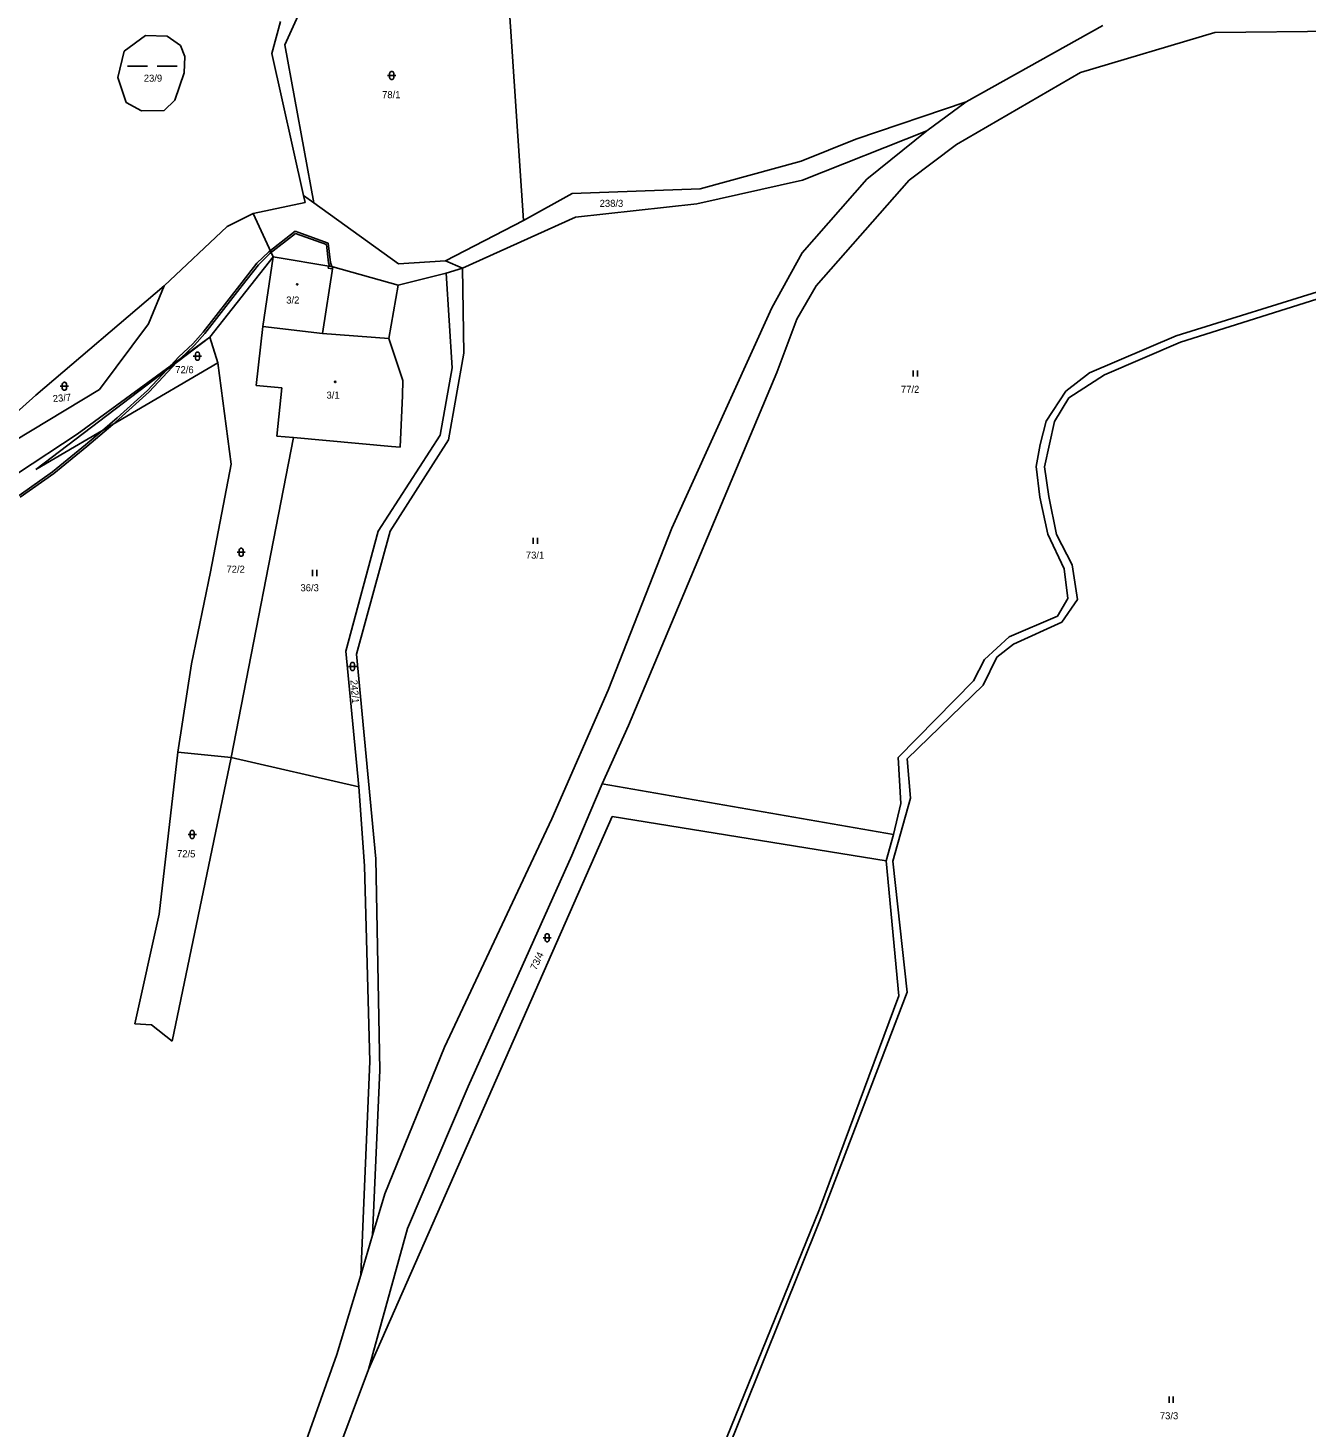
# Model space of a CAD drawing. Extents: x -811039 to -805820, y -1161436 to -1155864.
# Drawn here: x -809942.6 to -809634.1, y -1160806.6 to -1160468.8 of the extents above; entities that cross this region are included whole.
import ezdxf

# ---------------------------------------------------------------- set-up
doc = ezdxf.new("R2010")
doc.units = 0
for name, color, linetype in [('Default', 7, 'Continuous'), ('Hranice parcel', 7, 'Continuous'), ('Parcelní čísla', 7, 'Continuous'), ('Vnitřní kresba', 7, 'Continuous'), ('Věcná břemena k části', 7, 'Continuous'), ('Značky budov', 7, 'Continuous'), ('Značky kultur', 7, 'Continuous')]:
    doc.layers.add(name, color=color, linetype=linetype)

# ---------------------------------------------------------------- blocks, each defined once
blk = doc.blocks.new('306')
at = {"layer": 'Default'}
for p, q in [((-0.5, 1.5), (-0.5, 0)), ((0.5, 0), (0.5, 1.5))]:
    blk.add_line(p, q, dxfattribs=at)
blk = doc.blocks.new('316')
at = {"layer": 'Default'}
for points in [[(-1, 1), (0.27, 1), (1, 1)], [(-0.5, 1.5), (-0.4, 1.79), (-0.15, 1.97), (0.16, 1.97), (0.41, 1.79), (0.51, 1.5), (0.51, 0.5), (0.41, 0.21), (0.16, 0.03), (-0.15, 0.03), (-0.4, 0.21), (-0.5, 0.5), (-0.5, 1.5)]]:
    blk.add_lwpolyline(points, dxfattribs=at)
blk = doc.blocks.new('NAHRADNI_SYMBOL')
at = {"layer": 'Default'}
blk.add_lwpolyline([(0.09, 0.15), (0.18, 0), (0.09, -0.15), (-0.09, -0.15), (-0.18, 0), (-0.09, 0.15), (0.09, 0.15)], dxfattribs=at)
blk = doc.blocks.new('803')
at = {"layer": 'Default'}
for p, q in [((-7.5, 0), (-1.5, 0)), ((1.5, 0), (7.5, 0))]:
    blk.add_line(p, q, dxfattribs=at)
blk = doc.blocks.new('402')
at = {"layer": 'Default'}
blk.add_lwpolyline([(0.09, 0.15), (0.18, 0), (0.09, -0.15), (-0.09, -0.15), (-0.18, 0), (-0.09, 0.15), (0.09, 0.15)], dxfattribs=at)

msp = doc.modelspace()

# ---------------------------------------------------------------- linework, layer by layer
at = {"layer": 'Hranice parcel'}
for p, q in [((-809823.06, -1160515.27), (-809829.82, -1160416.25)), ((-809877.47, -1160465.79), (-809880.68, -1160472.84)), ((-809883.8, -1160474.97), (-809881.67, -1160467.23)), ((-809716.34, -1160486.61), (-809683.35, -1160468.18)), ((-809611.58, -1160469.43), (-809656.31, -1160469.91)), ((-809914.24, -1160470.6), (-809919.44, -1160474.42)), ((-809909.06, -1160470.76), (-809914.24, -1160470.6)), ((-809905.79, -1160473), (-809909.06, -1160470.76)), ((-809904.8, -1160475.71), (-809905.79, -1160473)), ((-809880.68, -1160472.84), (-809873.67, -1160511.01)), ((-809656.31, -1160469.91), (-809688.73, -1160479.53)), ((-809919.44, -1160474.42), (-809920.92, -1160480.71)), ((-809904.92, -1160479.6), (-809904.8, -1160475.71)), ((-809876.13, -1160509.23), (-809883.8, -1160474.97)), ((-809907.15, -1160486.22), (-809904.92, -1160479.6)), ((-809688.73, -1160479.53), (-809718.63, -1160496.94)), ((-809920.92, -1160480.71), (-809918.91, -1160486.78)), ((-809909.76, -1160488.69), (-809907.15, -1160486.22)), ((-809918.91, -1160486.78), (-809915.2, -1160488.75)), ((-809915.2, -1160488.75), (-809909.76, -1160488.69)), ((-809742.94, -1160495.64), (-809716.34, -1160486.61)), ((-809725.82, -1160493.62), (-809716.34, -1160486.61)), ((-809756.15, -1160500.96), (-809742.94, -1160495.64)), ((-809725.82, -1160493.62), (-809755.82, -1160505.53)), ((-809740.26, -1160505.29), (-809725.82, -1160493.62)), ((-809718.63, -1160496.94), (-809730.07, -1160505.55)), ((-809780.46, -1160507.64), (-809756.15, -1160500.96)), ((-809755.82, -1160505.53), (-809781.25, -1160511.19)), ((-809755.89, -1160523.01), (-809740.26, -1160505.29)), ((-809730.07, -1160505.55), (-809752.52, -1160530.98)), ((-809873.67, -1160511.01), (-809876.13, -1160509.23)), ((-809875.77, -1160510.89), (-809876.13, -1160509.23)), ((-809823.06, -1160515.27), (-809811.37, -1160508.77)), ((-809811.37, -1160508.77), (-809780.46, -1160507.64)), ((-809894.55, -1160516.72), (-809888.27, -1160513.54)), ((-809888.27, -1160513.54), (-809875.77, -1160510.89)), ((-809873.67, -1160511.01), (-809853.27, -1160525.68)), ((-809781.25, -1160511.19), (-809810.54, -1160514.41)), ((-809909.73, -1160530.98), (-809894.55, -1160516.72)), ((-809841.93, -1160524.94), (-809823.06, -1160515.27)), ((-809810.54, -1160514.41), (-809837.82, -1160526.72)), ((-809763.16, -1160536.3), (-809755.89, -1160523.01)), ((-809883.49, -1160524), (-809898.71, -1160543.36)), ((-809883.49, -1160524), (-809886, -1160540.84)), ((-809869.06, -1160526.43), (-809883.49, -1160524)), ((-809853.34, -1160530.87), (-809869.06, -1160526.43)), ((-809853.27, -1160525.68), (-809841.93, -1160524.94)), ((-809841.93, -1160524.94), (-809837.82, -1160526.72)), ((-809837.82, -1160526.72), (-809841.72, -1160527.92)), ((-809837.82, -1160526.72), (-809837.5, -1160547.29)), ((-809841.72, -1160527.92), (-809853.34, -1160530.87)), ((-809840.31, -1160550.77), (-809841.72, -1160527.92)), ((-809940.71, -1160557.39), (-809909.73, -1160530.98)), ((-809909.73, -1160530.98), (-809913.55, -1160540.17)), ((-809855.56, -1160543.75), (-809853.34, -1160530.87)), ((-809752.52, -1160530.98), (-809757.15, -1160539.08)), ((-809627.95, -1160531.37), (-809665.68, -1160543.05)), ((-809664.6, -1160544.58), (-809627.19, -1160532.74)), ((-809787.28, -1160589.46), (-809763.16, -1160536.3)), ((-809913.55, -1160540.17), (-809925.38, -1160556)), ((-809757.15, -1160539.08), (-809762.01, -1160551.92)), ((-809898.71, -1160543.36), (-809940.74, -1160575.35)), ((-809898.71, -1160543.36), (-809930.72, -1160566.77)), ((-809898.71, -1160543.36), (-809896.78, -1160549.56)), ((-809886, -1160540.84), (-809887.61, -1160555.05)), ((-809886, -1160540.84), (-809871.6, -1160542.54)), ((-809871.6, -1160542.54), (-809855.56, -1160543.75)), ((-809855.56, -1160543.75), (-809852.2, -1160553.81)), ((-809665.68, -1160543.05), (-809686.56, -1160552.03)), ((-809837.5, -1160547.29), (-809841.17, -1160568.14)), ((-809682.96, -1160552.46), (-809664.6, -1160544.58)), ((-809940.74, -1160575.35), (-809896.78, -1160549.56)), ((-809896.78, -1160549.56), (-809893.63, -1160574.06)), ((-809852.2, -1160553.81), (-809852.24, -1160557.47)), ((-809843.17, -1160567.06), (-809840.31, -1160550.77)), ((-809762.01, -1160551.92), (-809797.76, -1160637.1)), ((-809686.56, -1160552.03), (-809692.32, -1160556.39)), ((-809691.57, -1160558.03), (-809682.96, -1160552.46)), ((-809925.38, -1160556), (-809957.8, -1160575.57)), ((-809956.94, -1160571.85), (-809940.71, -1160557.39)), ((-809887.61, -1160555.05), (-809881.36, -1160555.62)), ((-809881.36, -1160555.62), (-809882.6, -1160567.26)), ((-809852.24, -1160557.47), (-809852.81, -1160569.93)), ((-809692.32, -1160556.39), (-809697.02, -1160563.66)), ((-809695.05, -1160563.78), (-809691.57, -1160558.03)), ((-809697.02, -1160563.66), (-809698.5, -1160569.3)), ((-809697.46, -1160574.68), (-809695.05, -1160563.78)), ((-809930.72, -1160566.77), (-809945.13, -1160576.29)), ((-809878.53, -1160567.62), (-809893.59, -1160644.8)), ((-809882.6, -1160567.26), (-809878.53, -1160567.62)), ((-809878.53, -1160567.62), (-809854.92, -1160569.78)), ((-809858.13, -1160590.22), (-809843.17, -1160567.06)), ((-809841.17, -1160568.14), (-809855.26, -1160590.19)), ((-809852.81, -1160569.93), (-809854.92, -1160569.78)), ((-809698.5, -1160569.3), (-809699.41, -1160574.62)), ((-809893.63, -1160574.06), (-809898.62, -1160599.98)), ((-809699.41, -1160574.62), (-809698.56, -1160581.98)), ((-809696.41, -1160581.8), (-809697.46, -1160574.68)), ((-809698.56, -1160581.98), (-809696.65, -1160590.93)), ((-809694.56, -1160590.99), (-809696.41, -1160581.8)), ((-809865.95, -1160619.17), (-809858.13, -1160590.22)), ((-809855.26, -1160590.19), (-809863.35, -1160619.86)), ((-809802.68, -1160628.59), (-809787.28, -1160589.46)), ((-809696.65, -1160590.93), (-809692.7, -1160599.28)), ((-809690.75, -1160598.32), (-809694.56, -1160590.99)), ((-809898.62, -1160599.98), (-809903.14, -1160622.22)), ((-809692.7, -1160599.28), (-809691.83, -1160606.41)), ((-809689.44, -1160606.7), (-809690.75, -1160598.32)), ((-809691.83, -1160606.41), (-809694.3, -1160610.72)), ((-809693.21, -1160612.17), (-809689.44, -1160606.7)), ((-809694.3, -1160610.72), (-809705.97, -1160615.68)), ((-809704.92, -1160617.46), (-809693.21, -1160612.17)), ((-809705.97, -1160615.68), (-809711.92, -1160621.18)), ((-809708.91, -1160620.56), (-809704.92, -1160617.46)), ((-809865.95, -1160619.17), (-809862.78, -1160651.89)), ((-809863.35, -1160619.86), (-809858.68, -1160669.24)), ((-809711.92, -1160621.18), (-809714.59, -1160626.3)), ((-809712.24, -1160627.36), (-809708.91, -1160620.56)), ((-809903.14, -1160622.22), (-809906.44, -1160643.5)), ((-809714.59, -1160626.3), (-809732.71, -1160644.81)), ((-809730.54, -1160645.15), (-809712.24, -1160627.36)), ((-809816.24, -1160659.57), (-809802.68, -1160628.59)), ((-809797.76, -1160637.1), (-809804.13, -1160651.13)), ((-809906.44, -1160643.5), (-809910.97, -1160682.61)), ((-809893.59, -1160644.8), (-809907.8, -1160713.26)), ((-809906.44, -1160643.5), (-809893.59, -1160644.8)), ((-809893.59, -1160644.8), (-809862.78, -1160651.89)), ((-809732.71, -1160644.81), (-809732.07, -1160655.93)), ((-809729.72, -1160654.63), (-809730.54, -1160645.15)), ((-809862.78, -1160651.89), (-809861.48, -1160670.94)), ((-809804.13, -1160651.13), (-809807.06, -1160658.14)), ((-809804.13, -1160651.13), (-809733.84, -1160663.41)), ((-809734.02, -1160669.85), (-809729.72, -1160654.63)), ((-809807.06, -1160658.14), (-809811.42, -1160668.42)), ((-809732.07, -1160655.93), (-809733.84, -1160663.41)), ((-809801.7, -1160659.02), (-809860.48, -1160792.45)), ((-809842.12, -1160714.67), (-809816.24, -1160659.57)), ((-809801.7, -1160659.02), (-809735.6, -1160669.71)), ((-809735.6, -1160669.71), (-809733.84, -1160663.41)), ((-809811.42, -1160668.42), (-809836.46, -1160724.22)), ((-809861.48, -1160670.94), (-809860.15, -1160718.11)), ((-809858.68, -1160669.24), (-809857.71, -1160720.21)), ((-809735.6, -1160669.71), (-809732.59, -1160702.29)), ((-809730.56, -1160701.42), (-809734.02, -1160669.85)), ((-809910.97, -1160682.61), (-809916.8, -1160709.07)), ((-809732.59, -1160702.29), (-809751.73, -1160753.81)), ((-809751.53, -1160756.27), (-809730.56, -1160701.42)), ((-809916.8, -1160709.07), (-809912.82, -1160709.31)), ((-809912.82, -1160709.31), (-809907.8, -1160713.26)), ((-809856.5, -1160750.08), (-809842.12, -1160714.67)), ((-809861.55, -1160750.2), (-809860.15, -1160718.11)), ((-809857.71, -1160720.21), (-809859.55, -1160760.03)), ((-809836.46, -1160724.22), (-809851.06, -1160758.42)), ((-809862.29, -1160769.69), (-809861.55, -1160750.2)), ((-809859.55, -1160760.03), (-809856.5, -1160750.08)), ((-809751.73, -1160753.81), (-809776.22, -1160814.21)), ((-809774.76, -1160814.15), (-809751.53, -1160756.27)), ((-809862.29, -1160769.69), (-809859.55, -1160760.03)), ((-809860.48, -1160792.45), (-809851.06, -1160758.42)), ((-809868.15, -1160788.8), (-809862.29, -1160769.69)), ((-809890.34, -1160851.73), (-809868.15, -1160788.8)), ((-809860.48, -1160792.45), (-809895.02, -1160884.48))]:
    msp.add_line(p, q, dxfattribs=at)
at = {"layer": 'Vnitřní kresba'}
msp.add_line((-809869.06, -1160526.43), (-809871.6, -1160542.54), dxfattribs=at)
at = {"layer": 'Věcná břemena k části'}
for p, q in [((-809884.51, -1160522.8), (-809878.14, -1160517.85)), ((-809878.05, -1160518.41), (-809884.17, -1160523.16)), ((-809878.14, -1160517.85), (-809870.17, -1160520.7)), ((-809870.63, -1160521.06), (-809878.05, -1160518.41)), ((-809887.39, -1160525.58), (-809884.51, -1160522.8)), ((-809884.17, -1160523.16), (-809887.03, -1160525.92)), ((-809870.14, -1160525.49), (-809870.63, -1160521.06)), ((-809870.17, -1160520.7), (-809869.65, -1160525.38)), ((-809890.94, -1160530.15), (-809887.39, -1160525.58)), ((-809887.03, -1160525.92), (-809890.92, -1160530.93)), ((-809870.24, -1160526.74), (-809870.15, -1160526.25)), ((-809869.25, -1160526.9), (-809870.24, -1160526.74)), ((-809870.15, -1160526.25), (-809869.89, -1160526.29)), ((-809869.89, -1160526.29), (-809870.14, -1160525.49)), ((-809869.34, -1160526.38), (-809869.89, -1160526.29)), ((-809869.89, -1160526.29), (-809869.34, -1160526.38)), ((-809869.65, -1160525.38), (-809869.34, -1160526.38)), ((-809869.34, -1160526.38), (-809869.17, -1160526.41)), ((-809869.17, -1160526.41), (-809869.25, -1160526.9)), ((-809900.36, -1160542.22), (-809890.94, -1160530.15)), ((-809890.92, -1160530.93), (-809899.98, -1160542.54)), ((-809902.83, -1160544.99), (-809900.36, -1160542.22)), ((-809899.98, -1160542.54), (-809902.48, -1160545.35)), ((-809906.2, -1160548.18), (-809902.83, -1160544.99)), ((-809902.48, -1160545.35), (-809905.84, -1160548.53)), ((-809906.67, -1160549.42), (-809913.41, -1160556.62)), ((-809909.05, -1160551.23), (-809906.67, -1160549.42)), ((-809908.14, -1160550.26), (-809906.2, -1160548.18)), ((-809905.97, -1160548.67), (-809908.14, -1160550.26)), ((-809905.84, -1160548.53), (-809905.97, -1160548.67)), ((-809913.75, -1160556.26), (-809909.05, -1160551.23)), ((-809921.09, -1160562.88), (-809913.75, -1160556.26)), ((-809913.41, -1160556.62), (-809920.71, -1160563.21)), ((-809924.63, -1160565.9), (-809921.09, -1160562.88)), ((-809920.71, -1160563.21), (-809922.18, -1160564.46)), ((-809928.7, -1160569.37), (-809924.63, -1160565.9)), ((-809922.18, -1160564.46), (-809928.42, -1160569.78)), ((-809924.63, -1160565.9), (-809922.18, -1160564.46)), ((-809922.18, -1160564.46), (-809924.63, -1160565.9)), ((-809936.71, -1160575.9), (-809928.7, -1160569.37)), ((-809928.42, -1160569.78), (-809936.4, -1160576.3)), ((-809944.75, -1160581.6), (-809936.71, -1160575.9)), ((-809936.4, -1160576.3), (-809944.46, -1160582.01))]:
    msp.add_line(p, q, dxfattribs=at)
msp.add_lwpolyline([(-809883.49, -1160524), (-809888.27, -1160513.54), (-809875.77, -1160510.89), (-809876.13, -1160509.23), (-809873.67, -1160511.01), (-809853.27, -1160525.68), (-809841.93, -1160524.94), (-809837.82, -1160526.72), (-809841.72, -1160527.92), (-809853.34, -1160530.87), (-809869.06, -1160526.43)], close=True, dxfattribs=at)

# ---------------------------------------------------------------- block references
at = {"layer": 'Značky budov'}
msp.add_blockref('402', (-809877.67, -1160530.65), dxfattribs=at)
at = {"layer": 'Značky kultur', "xscale": 0.8, "yscale": 0.8000000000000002}
msp.add_blockref('803', (-809912.61, -1160478.03), dxfattribs=at)
at = {"layer": 'Značky kultur'}
for name, p in [('316', (-809854.89, -1160481.25)), ('316', (-809901.73, -1160549)), ('NAHRADNI_SYMBOL', (-809868.54, -1160554.17)), ('306', (-809728.57, -1160552.91)), ('316', (-809933.84, -1160556.25)), ('316', (-809891.19, -1160596.3)), ('306', (-809820.23, -1160593.27)), ('306', (-809873.46, -1160601.03)), ('316', (-809864.33, -1160623.83)), ('316', (-809903, -1160664.38)), ('316', (-809817.38, -1160689.28)), ('306', (-809666.86, -1160800.48))]:
    msp.add_blockref(name, p, dxfattribs=at)

# ---------------------------------------------------------------- texts
at = {"layer": 'Parcelní čísla'}
for s, p in [('23/9', (-809914.67, -1160481.76)), ('78/1', (-809857.2, -1160485.74)), ('238/3', (-809804.72, -1160511.96)), ('3/2', (-809880.32, -1160535.29)), ('3/1', (-809870.6, -1160558.22)), ('77/2', (-809732.06, -1160556.83)), ('73/1', (-809822.52, -1160596.83)), ('72/2', (-809894.73, -1160600.22)), ('36/3', (-809876.88, -1160604.7)), ('73/3', (-809669.6, -1160804.47))]:
    msp.add_text(s, height=1.7, dxfattribs=at).set_placement(p)
for s, rotation, p in [('72/6', 359.474, (-809907.08, -1160552.07)), ('23/7', 4.927, (-809936.55, -1160559.09)), ('242/1', 274.733, (-809864.85, -1160626.15)), ('72/5', 358.901, (-809906.67, -1160668.84)), ('73/4', 64.916, (-809820.03, -1160696.24))]:
    msp.add_text(s, height=1.7, rotation=rotation, dxfattribs=at).set_placement(p)

doc.saveas('drawing.dxf')
